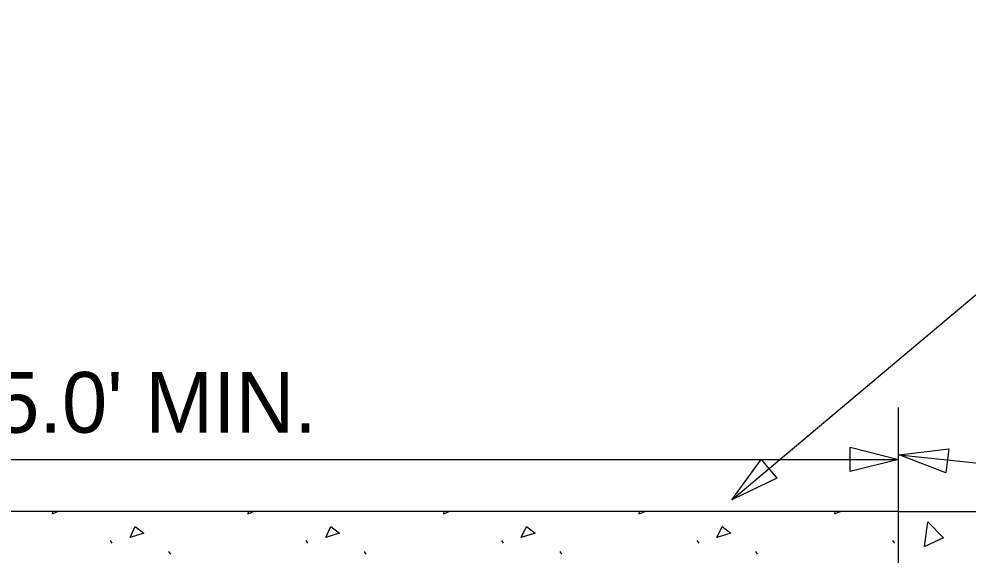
# Model space of a CAD drawing. Extents: x 9992 to 10079.1, y 10009.9 to 10072.5.
# Drawn here: x 10033.1 to 10049.41, y 10062.98 to 10072.2 of the extents above; entities that cross this region are included whole.
import ezdxf

# ---------------------------------------------------------------- set-up
doc = ezdxf.new("R2010")
doc.units = 0
for name, color, linetype in [('Default', 7, 'Continuous'), ('G-ANNO-TEXT', 7, 'Continuous'), ('G-DETL-OTLN', 7, 'Continuous'), ('G-DETL-PATT', 7, 'Continuous')]:
    doc.layers.add(name, color=color, linetype=linetype)

# ---------------------------------------------------------------- blocks, each defined once
blk = doc.blocks.new('TERARR')
at = {"layer": 'Default'}
blk.add_lwpolyline([(-0.667, 0.167), (0, 0), (-0.667, -0.167)], close=True, dxfattribs=at)

msp = doc.modelspace()

# ---------------------------------------------------------------- linework, layer by layer
at = {"layer": 'Default'}
for points in [[(10033.671, 10063.687), (10033.677, 10063.733)], [(10033.772, 10063.733), (10033.678, 10063.69)], [(10037.03, 10063.687), (10037.037, 10063.733)], [(10037.131, 10063.733), (10037.037, 10063.69)]]:
    msp.add_lwpolyline(points, dxfattribs=at)
at = {"layer": 'G-ANNO-TEXT'}
for p, q in [((10048.203, 10063.733), (10048.203, 10065.518)), ((10024.858, 10064.626), (10048.203, 10064.626)), ((10048.203, 10063.733), (10050.573, 10063.733))]:
    msp.add_line(p, q, dxfattribs=at)
for points in [[(10045.34, 10063.93), (10055.169, 10072.198), (10056.297, 10072.198)], [(10048.21, 10064.706), (10057.299, 10063.754), (10058.262, 10063.754)]]:
    msp.add_lwpolyline(points, dxfattribs=at)
at = {"layer": 'G-DETL-OTLN'}
msp.add_lwpolyline([(10024.858, 10061.294), (10048.203, 10061.294), (10048.203, 10063.733), (10024.858, 10063.733)], close=True, dxfattribs=at)
at = {"layer": 'G-DETL-PATT'}
for p, q in [((10034.662, 10063.235), (10034.692, 10063.19)), ((10038.022, 10063.235), (10038.051, 10063.19)), ((10041.381, 10063.235), (10041.411, 10063.19)), ((10044.74, 10063.235), (10044.77, 10063.19)), ((10048.1, 10063.235), (10048.13, 10063.19)), ((10035.667, 10063.045), (10035.697, 10063.001)), ((10039.026, 10063.045), (10039.056, 10063.001)), ((10042.386, 10063.045), (10042.415, 10063.001)), ((10045.745, 10063.045), (10045.775, 10063.001))]:
    msp.add_line(p, q, dxfattribs=at)
for points in [[(10040.39, 10063.687), (10040.396, 10063.733)], [(10040.49, 10063.733), (10040.397, 10063.69)], [(10043.749, 10063.687), (10043.755, 10063.733)], [(10043.85, 10063.733), (10043.756, 10063.69)], [(10047.108, 10063.687), (10047.115, 10063.733)], [(10047.209, 10063.733), (10047.115, 10063.69)], [(10035.004, 10063.287), (10035.094, 10063.474), (10035.243, 10063.362), (10035.004, 10063.287)], [(10038.364, 10063.287), (10038.453, 10063.474), (10038.602, 10063.362), (10038.364, 10063.287)], [(10041.723, 10063.287), (10041.813, 10063.474), (10041.962, 10063.362), (10041.723, 10063.287)], [(10045.082, 10063.287), (10045.172, 10063.474), (10045.321, 10063.362), (10045.082, 10063.287)], [(10048.645, 10063.13), (10048.704, 10063.556), (10048.971, 10063.28), (10048.652, 10063.132)]]:
    msp.add_lwpolyline(points, dxfattribs=at)

# ---------------------------------------------------------------- block references
at = {"layer": 'G-ANNO-TEXT', "xscale": 1.25, "yscale": 1.25}
msp.add_blockref('TERARR', (10048.203, 10064.626), dxfattribs=at)
at = {"layer": 'G-ANNO-TEXT', "yscale": 1.25}
for p, xscale, rotation in [((10048.21, 10064.706), 1.2500000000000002, 172.79141056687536), ((10045.34, 10063.93), 1.25, -139.93067788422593)]:
    msp.add_blockref('TERARR', p, dxfattribs=dict(at, xscale=xscale, rotation=rotation))

# ---------------------------------------------------------------- texts
at = {"layer": 'G-ANNO-TEXT'}
msp.add_text("5.0' MIN.", height=1.044, dxfattribs=at).set_placement((10032.671, 10065.086))

doc.saveas('drawing.dxf')
